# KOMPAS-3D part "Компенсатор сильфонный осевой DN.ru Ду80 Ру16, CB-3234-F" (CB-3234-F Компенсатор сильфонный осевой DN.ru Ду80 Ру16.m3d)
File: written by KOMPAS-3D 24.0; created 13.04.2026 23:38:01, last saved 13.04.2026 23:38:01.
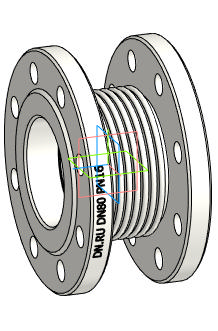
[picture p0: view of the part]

Document properties: Автор: DN.RU; Полное имя файла: D:\PROJECT CAD\DN.RU\...198(ACTUALE). CB-3234-F Компенсатор сильфонный осевой DN.ru\Исходники\DN80\CB-3234-F Компенсатор сильфонный осевой DN.ru Ду80 Ру16.m3d

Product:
- Body: Твердое тело1  | qty 1
    Масса: 8.733566
- Part/product: Компенсатор сильфонный осевой DN.ru Ду80 Ру16  | designation CB-3234-F
    Масса: 7
    Раздел спецификации: Прочие изделия
    Комментарий: D140-02115
    Примечание: D140-02115
    additional columns: Типовые

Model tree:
1. Твердое тело1  (labels: Твердое тело1)

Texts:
  CB-3234-F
